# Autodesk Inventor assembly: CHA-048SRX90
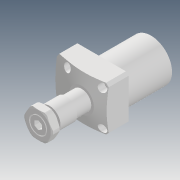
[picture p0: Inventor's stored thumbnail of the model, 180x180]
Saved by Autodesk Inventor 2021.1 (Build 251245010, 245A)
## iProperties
Created: 2019-05
Part Number: CHA-048SRX90
Description: STEP AP203
Document SubType Name: Assembly
Designer: user
Title: CHA-048SRX90.STEP
Revision Number: ÈÎºÎ
Sending System: SolidWorks 2017
Preprocessor: SwSTEP 2.0
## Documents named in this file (5)
- D:\Vault_2016\Projekty\Clamptek\Hydraulic\CHA\CHA\CHA-048\Inventor\CHA-048SRX90\CHA-048SRX90.iam
- D:\Vault_2016\Projekty\Clamptek\Hydraulic\CHA\CHA\CHA-048\Inventor\CHA-048SRX90\CHA-048±¾Ìå.ipt
- D:\Vault_2016\Projekty\Clamptek\Hydraulic\CHA\CHA\CHA-048\Inventor\CHA-048SRX90\CHA-048S×¶Ì×.ipt
- D:\Vault_2016\Projekty\Clamptek\Hydraulic\CHA\CHA\CHA-048\Inventor\CHA-048SRX90\CHA-048S»îÈû¸Ë.ipt
- D:\Vault_2016\Projekty\Clamptek\Hydraulic\CHA\CHA\CHA-048\Inventor\CHA-048SRX90\CHA-048ÂÝÄ¸.ipt
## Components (4 placed, 4 different names)
1. CHA-048±¾Ìå_1
2. CHA-048S×¶Ì×_2
3. CHA-048S»îÈû¸Ë_3
4. CHA-048ÂÝÄ¸_4
